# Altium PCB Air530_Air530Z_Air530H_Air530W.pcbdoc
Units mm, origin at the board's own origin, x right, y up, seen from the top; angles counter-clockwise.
Board outline 74.84 x 26.55 mm, 2 copper layers (Top Layer, Bottom Layer); 4 components, 0 nets, 56 pads, 0 vias.
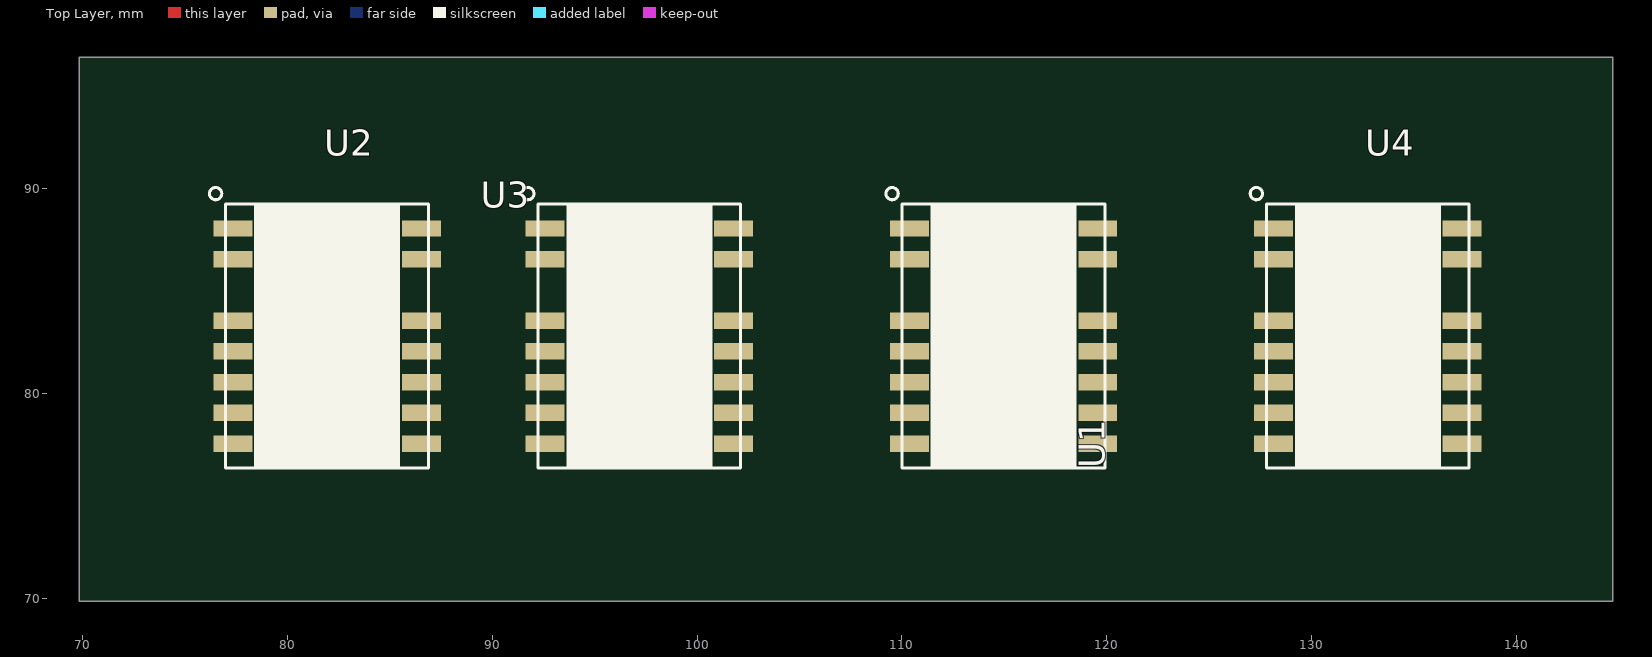
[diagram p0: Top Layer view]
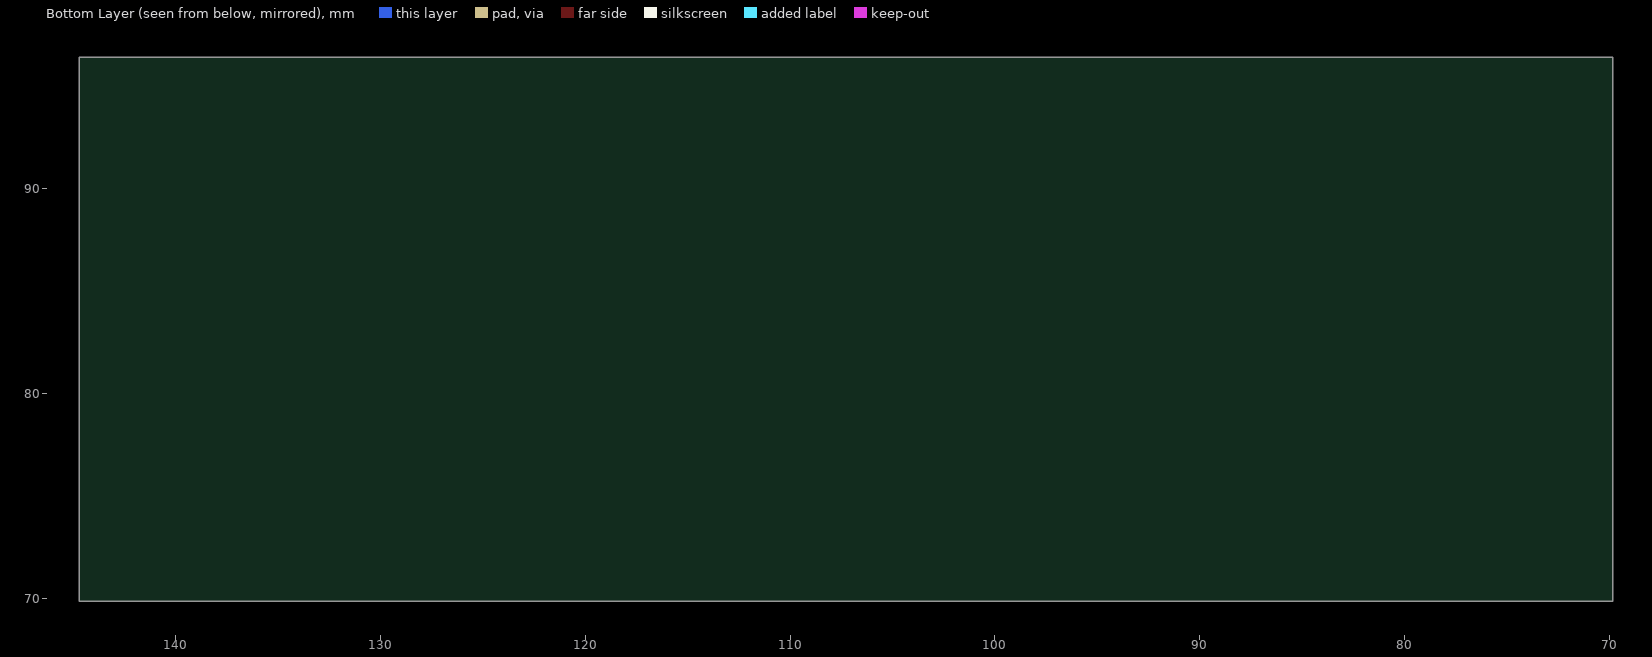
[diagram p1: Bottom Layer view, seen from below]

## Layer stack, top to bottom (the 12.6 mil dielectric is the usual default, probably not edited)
Top Layer: signal copper (thickness not stored)
Dielectric: dielectric 0.32, FR-4, Dk 4.8
Bottom Layer: signal copper (thickness not stored)

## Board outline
144.689,69.85 69.85,69.85 69.85,96.4 144.689,96.4

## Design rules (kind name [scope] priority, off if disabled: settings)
BoardOutlineClearance safeClearance [All] p0: genericclearance=0.254 ignorepadtopadclearanceinfootprint=FALSE except(0: Region-OutlineEdge Poly-OutlineEdge Text-OutlineEdge Sheet-OutlineEdge Hole-OutlineEdge Track-CutoutEdge SMDPad-CutoutEdge THPad-CutoutEdge Via-CutoutEdge Fill-CutoutEdge Region-CutoutEdge Poly-CutoutEdge Text-CutoutEdge Sheet-CutoutEdge Hole-CutoutEdge Arc-SplitContinuation Track-SplitContinuation SMDPad-SplitContinuation THPad-SplitContinuation Via-SplitContinuation Fill-SplitContinuation Poly-SplitContinuation Region-SplitContinuation Text-SplitContinuation; 0.152: Track-OutlineEdge SMDPad-OutlineEdge THPad-OutlineEdge Via-OutlineEdge Fill-OutlineEdge)
Clearance safeClearance [All] p1: gap=0.178 ignorepadtopadclearanceinfootprint=FALSE except(0: Region-Track Poly-Track Region-SMDPad Poly-SMDPad Region-THPad Poly-THPad Region-Via Poly-Via Region-Fill Poly-Fill Text-Fill Track-Region SMDPad-Region THPad-Region Via-Region Fill-Region Region-Region Poly-Region Text-Region Sheet-Region Hole-Region Track-Poly SMDPad-Poly THPad-Poly Via-Poly Fill-Poly Region-Poly Poly-Poly Text-Poly Sheet-Poly Hole-Poly Fill-Text Region-Text Poly-Text Text-Text Sheet-Text Hole-Text Region-Sheet Poly-Sheet Text-Sheet Sheet-Sheet Hole-Sheet Region-Hole Poly-Hole Text-Hole Sheet-Hole; 0.152: Track-Track SMDPad-Track THPad-Track Via-Track Fill-Track Text-Track Sheet-Track Hole-Track Track-SMDPad SMDPad-SMDPad THPad-SMDPad Via-SMDPad Fill-SMDPad Text-SMDPad Sheet-SMDPad Hole-SMDPad Track-THPad SMDPad-THPad THPad-THPad Via-THPad Fill-THPad Text-THPad Sheet-THPad Hole-THPad Track-Via SMDPad-Via THPad-Via Via-Via Fill-Via Text-Via Sheet-Via Hole-Via Track-Fill SMDPad-Fill THPad-Fill Via-Fill Fill-Fill Sheet-Fill Hole-Fill Track-Text SMDPad-Text THPad-Text Via-Text Track-Sheet SMDPad-Sheet THPad-Sheet Via-Sheet Fill-Sheet Track-Hole SMDPad-Hole THPad-Hole Via-Hole Fill-Hole Hole-Hole)
PasteMaskExpansion Common [All] p1: expansion=0
SolderMaskExpansion Common [All] p1: useseparateexpansions=TRUE expansion=0 expansionbottom=0
Width trackWidth [All] p1: maxlimit=12 minlimit=12 preferedwidth=12

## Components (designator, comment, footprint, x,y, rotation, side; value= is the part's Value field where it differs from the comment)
U1 "AIR530H@AIR530W" AIR530W 119.909,76.35 r90 top
U2 "AIR530@AIR530W" AIR530W 86.889,76.35 r90 top
U3 "AIR530Z@AIR530W" AIR530W 102.129,76.35 r90 top
U4 "AIR530W" AIR530W 137.689,76.35 r90 top

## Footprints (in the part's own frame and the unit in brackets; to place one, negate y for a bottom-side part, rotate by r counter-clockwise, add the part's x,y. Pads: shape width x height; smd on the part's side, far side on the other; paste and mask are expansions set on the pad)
AIR530W [mm]
  rect 0.8x1.9 smd: 1(11.7,9.55) 2(10.2,9.55) 3(7.2,9.55) 4(5.7,9.55) 5(4.2,9.55) 6(2.7,9.55) 7(1.2,9.55) 8(1.2,0.35) 9(2.7,0.35) 10(4.2,0.35) 11(5.7,0.35) 12(7.2,0.35) 13(10.2,0.35) 14(11.7,0.35)
  silkscreen extent 0,0 13.7,10.69

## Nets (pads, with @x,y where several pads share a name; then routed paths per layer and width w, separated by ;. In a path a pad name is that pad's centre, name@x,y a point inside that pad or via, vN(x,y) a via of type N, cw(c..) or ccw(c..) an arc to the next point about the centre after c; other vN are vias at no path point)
pads on no net: U1.1 U1.2 U1.3 U1.4 U1.5 U1.6 U1.7 U1.8 U1.9 U1.10 U1.11 U1.12 U1.13 U1.14 U2.1 U2.2 U2.3 U2.4 U2.5 U2.6 U2.7 U2.8 U2.9 U2.10 U2.11 U2.12 U2.13 U2.14 U3.1 U3.2 U3.3 U3.4 U3.5 U3.6 U3.7 U3.8 U3.9 U3.10 U3.11 U3.12 U3.13 U3.14 U4.1 U4.2 U4.3 U4.4 U4.5 U4.6 U4.7 U4.8 U4.9 U4.10 U4.11 U4.12 U4.13 U4.14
